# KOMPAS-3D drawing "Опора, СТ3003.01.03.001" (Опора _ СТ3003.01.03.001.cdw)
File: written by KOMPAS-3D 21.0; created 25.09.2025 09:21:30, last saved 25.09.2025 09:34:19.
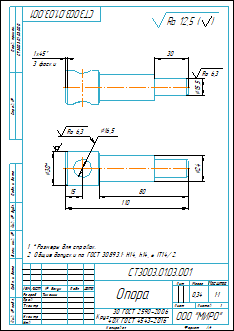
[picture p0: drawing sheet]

Sheet 1: A4, portrait

Document properties: Полное имя файла: ..\..\3D\Струбцина _ СТ3003.01.03.000\Опора _ СТ3003.01.03.001.m3d; Знак неуказанной шероховатости: 4; Параметр неуказанной шероховатости: Ra 12,5; Масса: 0.339602

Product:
- Part/product: Опора  | designation СТ3003.01.03.001
    Материал: Круг$d30 ГОСТ 2590-2006;40Х ГОСТ 4543-2016$ (density 7850 kg/m3)
    Масса: 0.339602
    Форматы листов документа: A4

Title block, sheet 1: Наименование: Опора; designation: СТ3003.01.03.001; Материал: Круг 30 ГОСТ 2590-2006 40Х ГОСТ 4543-2016; Масса: 0,34; Количество листов документа: 1; organisation: ООО "МИРО"; Форматы листов документа: A4; stored path: C:\Users\1\Yandex.Disk\Документы\Новая папка\Стапель №2\Стапель _ СТ3003.00.00.000\Опора _ СТ3003.01.00.000\2D\Струбцина _ СТ3003.01.03.000\Опора _ СТ3003.01.03.001.cdw; Разработал: Тимонин

Views: Вид 1, Спереди, Проекционный вид 2
Referenced files in C:\Users\1\Yandex.Disk\Документы\Новая папка\Стапель №2\Стапель _ СТ3003.00.00.000\Опора _ СТ3003.01.00.000\3D\Струбцина _ СТ3003.01.03.000\: Опора _ СТ3003.01.03.001.m3d
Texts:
  Ra 6,3
  Ra 12,5
  Ra 12,5 ( )
  СТ3003.01.03.000
  СТ3003.01.03.001 Опора
Dimensions and other numbers on the sheet: 15,5; 30; 1; 3 фаски; 15; 110; 80; 24; 16,5; 1:1; 0,34

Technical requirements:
  *Размеры для справок.
  Общие допуски по ГОСТ 30893.1: Н14, h14, ± IT14/2.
